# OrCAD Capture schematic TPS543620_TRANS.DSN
size D; title: TPS543620 4V to 18V Input, 6A Synchronous Step-Down Converter; rev: 1.0; note: Datasheet: SLUSDR5B     EVM: SLVUBQ1A; note: with Internally Compensated Advanced CurrentMode Control
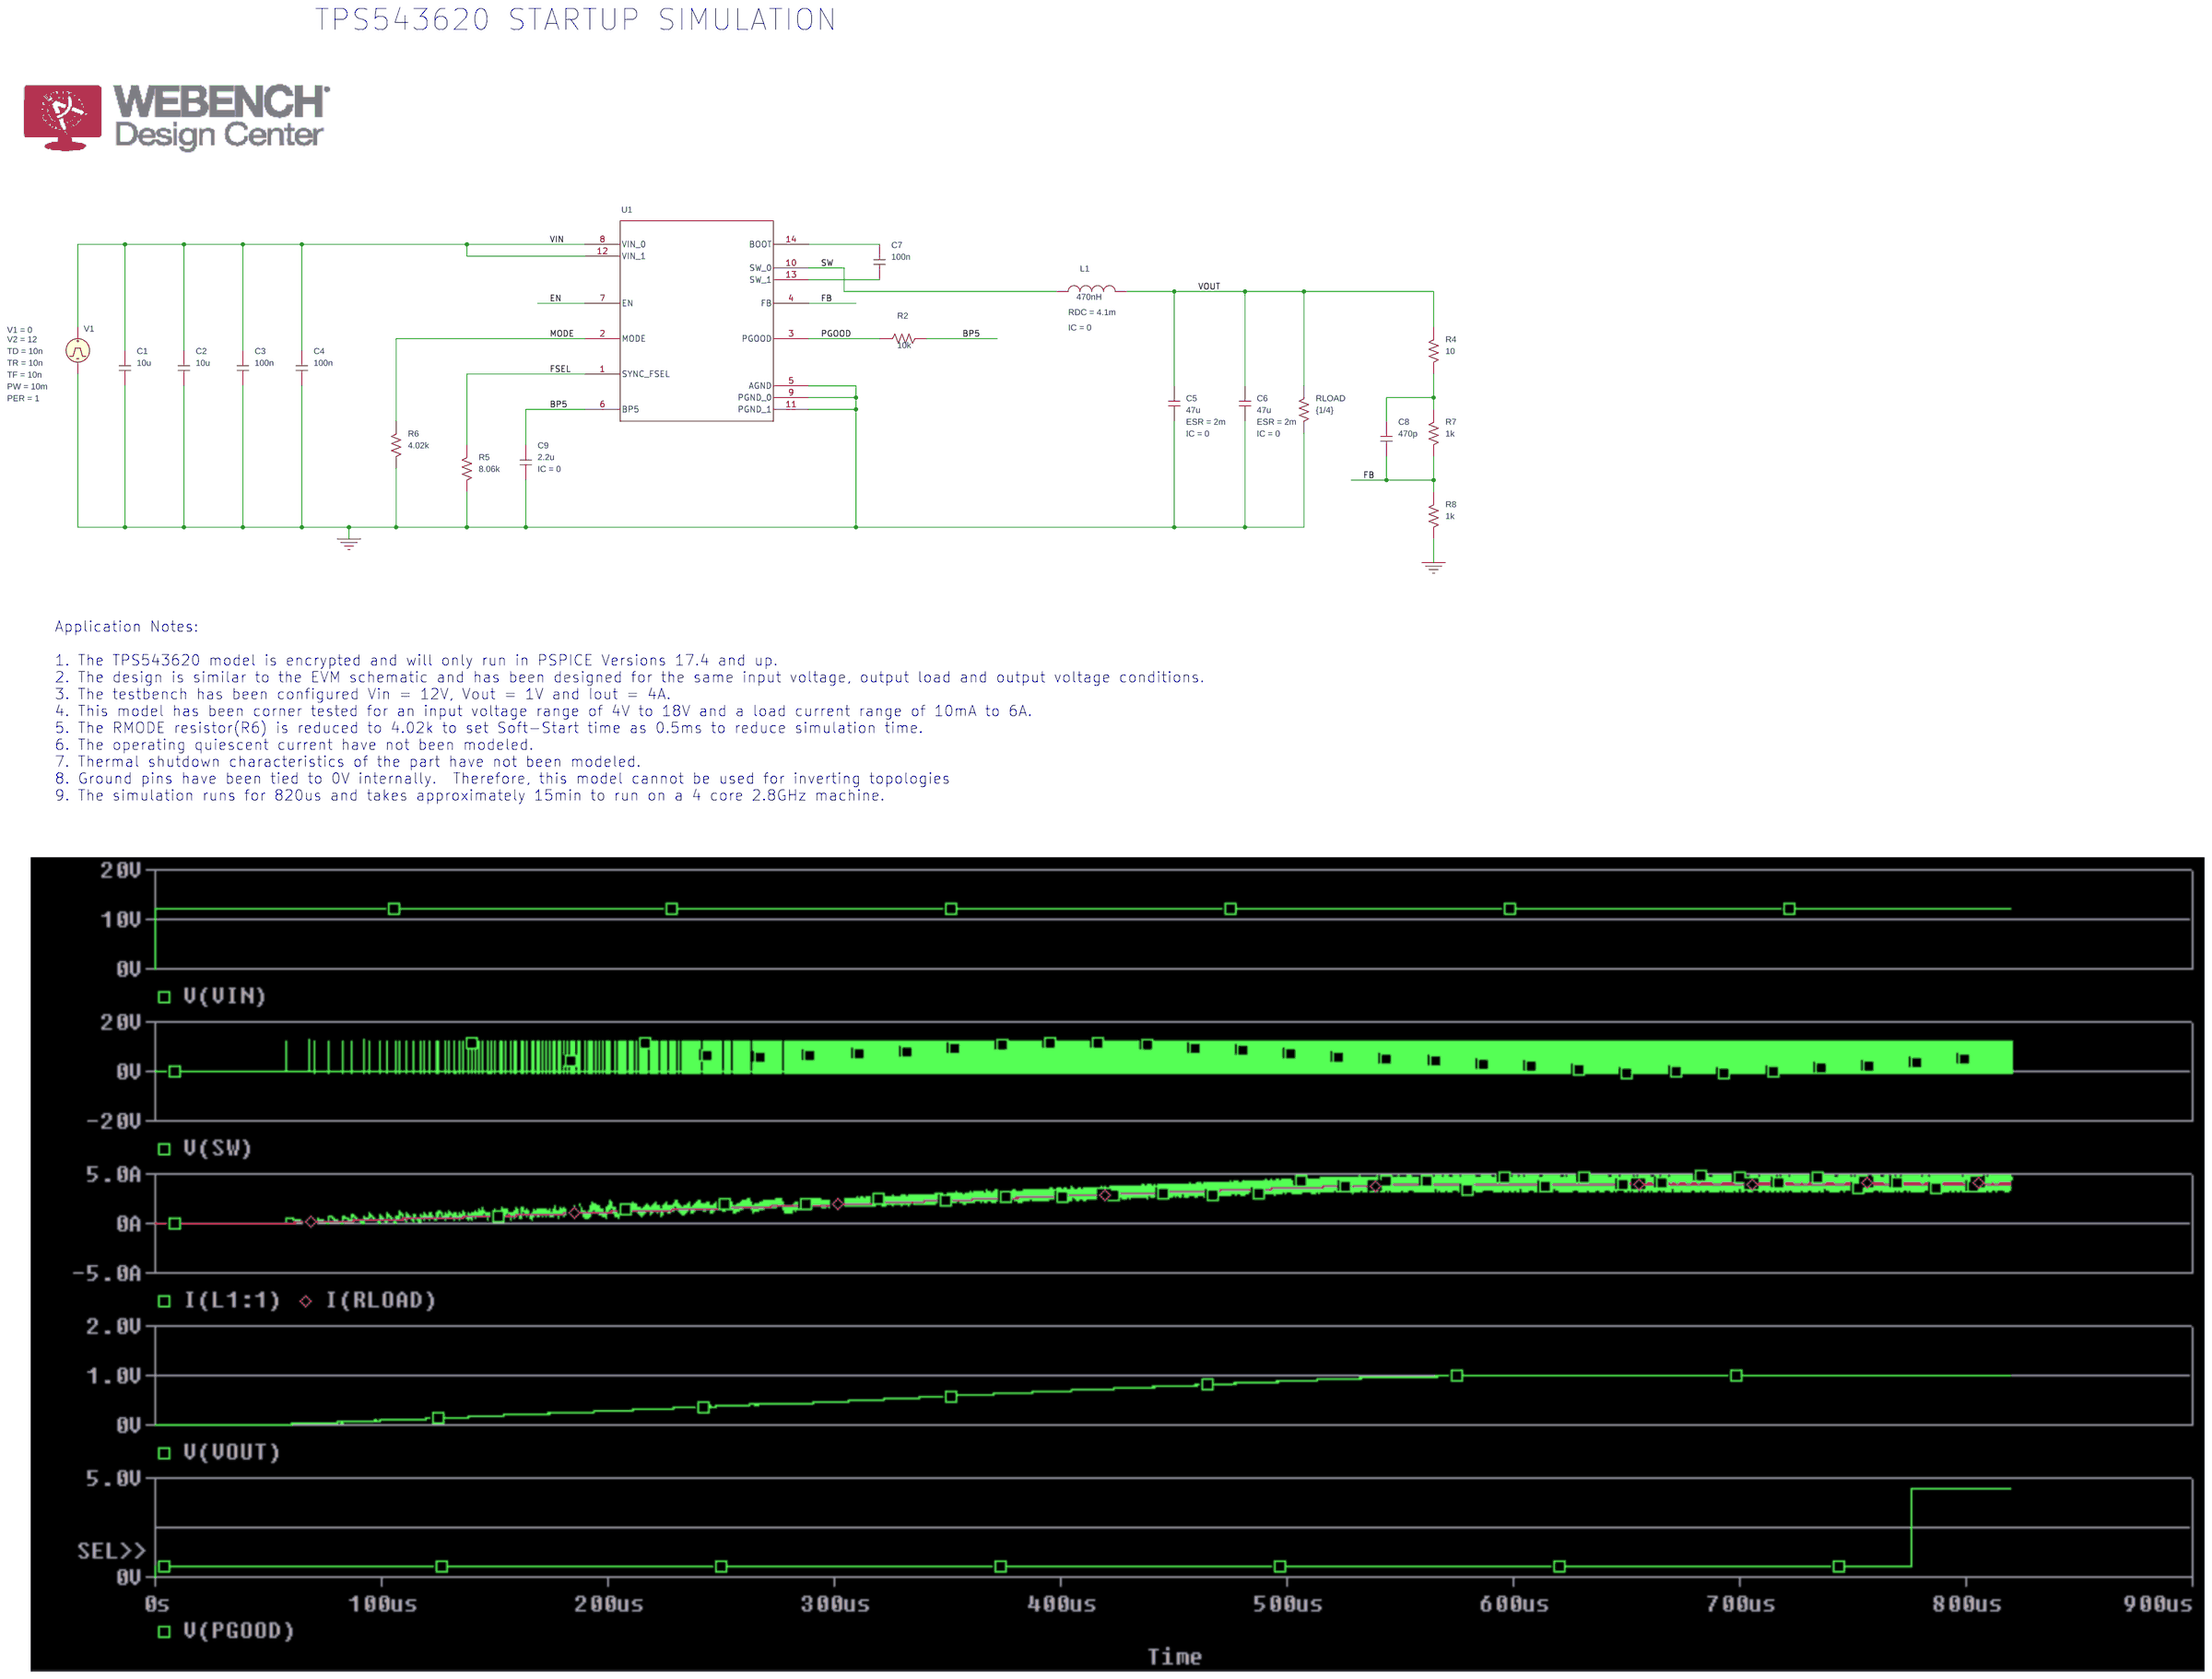
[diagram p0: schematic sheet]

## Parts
C1  10u  [cap196]
C2  10u  [cap196]
C3  100n  [cap196]
C4  100n  [cap196]
C5  47u  [RAD/CK05]
C6  47u  [RAD/CK05]
C7  100n  [cap196]
C8  470p  [cap196]
C9  2.2u  [cap196]
L1  470nH  [DISC/.350x.175/LS.200x.100/.034]
R2  10k  [AXRC05]
R4  10  [AXRC05]
R5  8.06k  [AXRC05]
R6  4.02k  [AXRC05]
R7  1k  [AXRC05]
R8  1k  [AXRC05]
RLOAD  {1/4}  [AXRC05]
U1  TPS543620RPY_TRANS  [RPY0014A-MFG]
V1  VPULSE

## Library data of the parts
C1-C4 C7 C8 = C
C5 C6 = C: AppProp: InductiveSlave:;SRF:;PrevCap:22u;PrevESL:; ESR: 2m; IC: 0
C9 = C: IC: 0
L1 = L: AppProp: SRF:; IC: 0; RDC: 4.1m
R2 R4-R8 RLOAD = R
U1 = TPS543620RPY_TRANS: PSpiceTemplate: X^@REFDES  %SYNC_FSEL %PGND_0 %FB %VIN_1 %EN %PGOOD %MODE %BP5 %SW_0 %SW_1 %BOOT %AGND %PGND_1 %VIN_0 @MODEL
V1 = VPULSE: PER: 1; PW: 10m; TD: 10n; TF: 10n; TR: 10n; V1: 0; V2: 12

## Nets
VIN: C1.1 C2.1 C3.1 C4.1 U1.8(VIN_0) U1.12(VIN_1) V1.1(+)
0: C1.2 C2.2 C3.2 C4.2 C5.2 C6.2 C9.2 R5.2 R6.2 R8.2 RLOAD.2 U1.5(AGND) U1.9(PGND_0) U1.11(PGND_1) V1.2(-)
BP5: C9.1 R2.2 U1.6(BP5)
EN: U1.7(EN)
FB: C8.2 R7.2 R8.1 U1.4(FB)
FSEL: R5.1 U1.1(SYNC_FSEL)
MODE: R6.1 U1.2(MODE)
PGOOD: R2.1 U1.3(PGOOD)
SW: L1.1 U1.10(SW_0)
VOUT: C5.1 C6.1 L1.2 R4.1 RLOAD.1
N16771999: C7.1 U1.14(BOOT)
N16772003: C7.2 U1.13(SW_1)
N16772420: C8.1 R4.2 R7.1

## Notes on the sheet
- TPS543620 STARTUP SIMULATION
- Application Notes:
  1. The TPS543620 model is encrypted and will only run in PSPICE Versions 17.4 and up.
  2. The design is similar to the EVM schematic and has been designed for the same input voltage, output load and output voltage conditions.
  3. The testbench has been configured Vin = 12V, Vout = 1V and Iout = 4A.
  4. This model has been corner tested for an input voltage range of 4V to 18V and a load current range of 10mA to 6A.
  5. The RMODE resistor(R6) is reduced to 4.02k to set Soft-Start time as 0.5ms to reduce simulation time.
  6. The operating quiescent current have not been modeled.
  7. Thermal shutdown characteristics of the part have not been modeled.
  8. Ground pins have been tied to 0V internally.  Therefore, this model cannot be used for inverting topologies
  9. The simulation runs for 820us and takes approximately 15min to run on a 4 core 2.8GHz machine.
